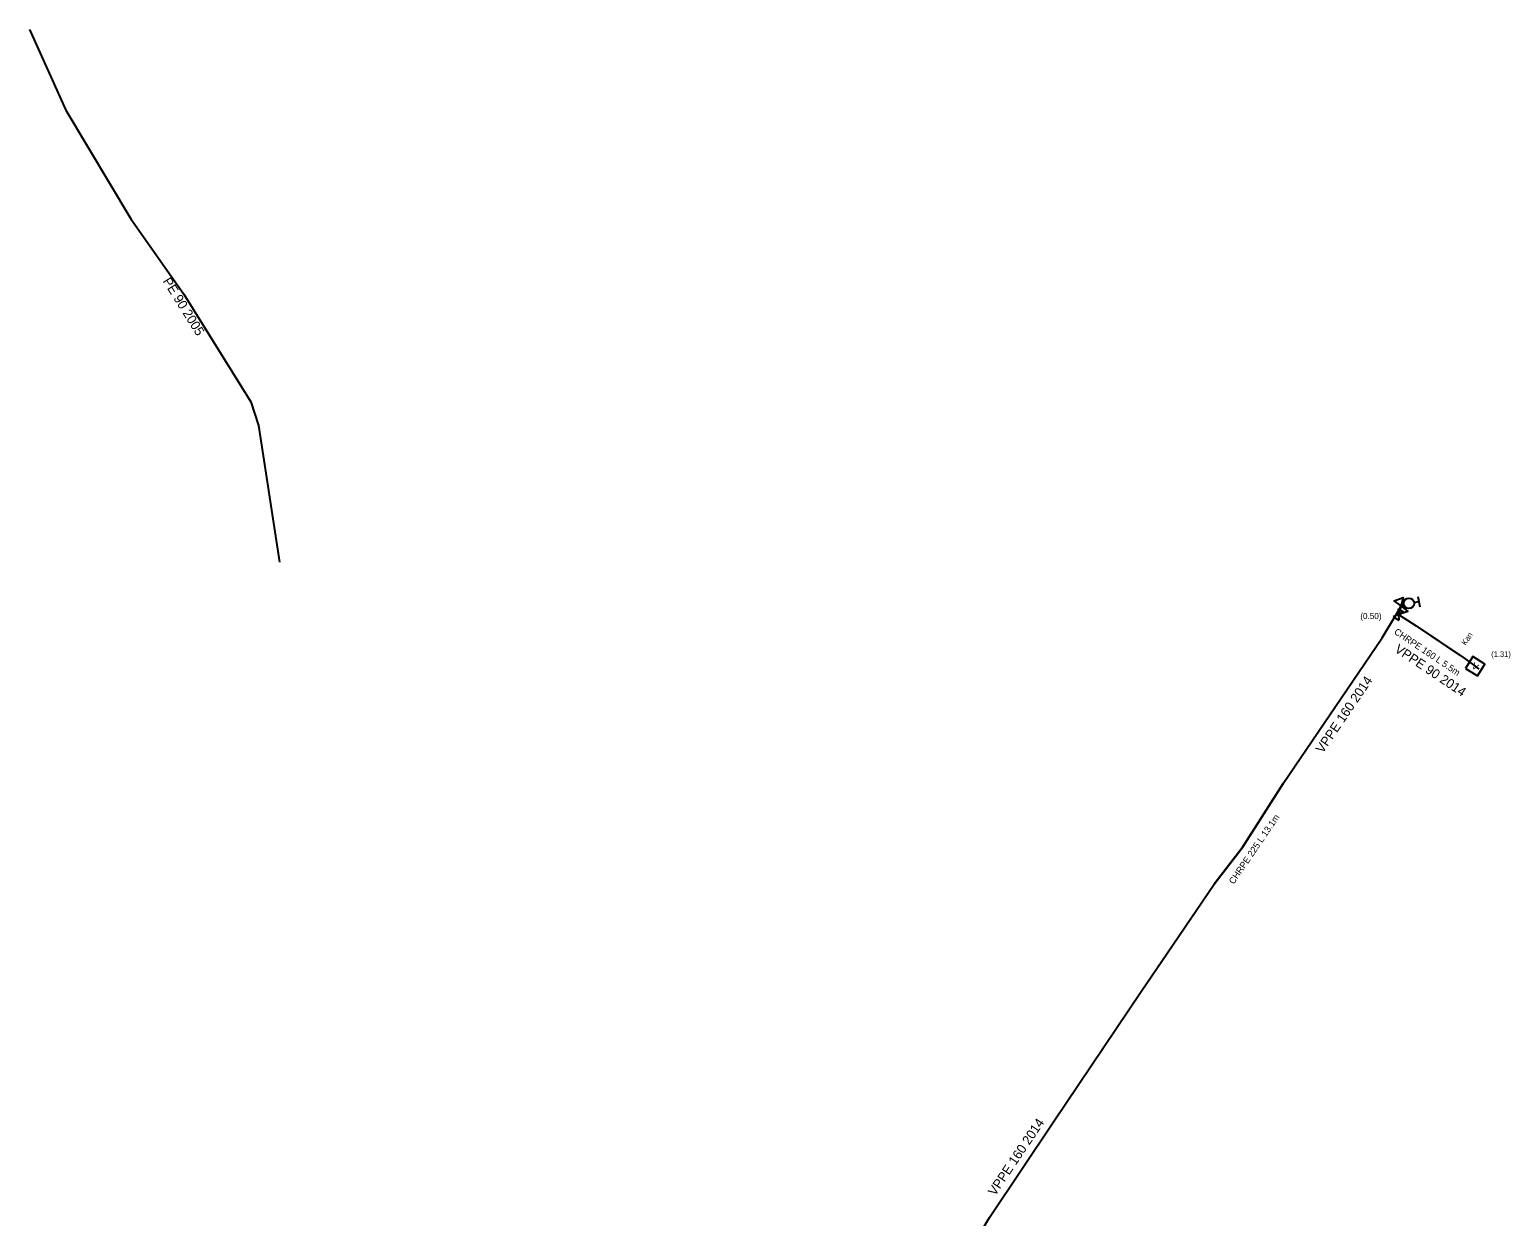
# Model space of a CAD drawing. Extents: x -539692 to -539259, y -1156467 to -1155971.
# Drawn here: x -539417.2 to -539259.2, y -1156098 to -1155971.4 of the extents above; entities that cross this region are included whole.
import ezdxf

# ---------------------------------------------------------------- set-up
doc = ezdxf.new("R2010")
doc.units = 0
for name, color, linetype in [('Vrstva 11', 7, 'Continuous'), ('Vrstva 15', 7, 'Continuous'), ('Vrstva 18', 7, 'Continuous'), ('Vrstva 26', 7, 'Continuous'), ('Vrstva 28', 7, 'Continuous'), ('Vrstva 32', 7, 'Continuous'), ('Vrstva 37', 7, 'Continuous'), ('Vrstva 55', 7, 'Continuous'), ('Vrstva 57', 7, 'Continuous'), ('Vrstva 58', 7, 'Continuous'), ('Vrstva 7', 7, 'Continuous')]:
    doc.layers.add(name, color=color, linetype=linetype)

msp = doc.modelspace()

# ---------------------------------------------------------------- linework, layer by layer
at = {"layer": 'Vrstva 11'}
for points in [[(-539417.223, -1155971.388), (-539413.37, -1155979.97), (-539406.41, -1155991.57), (-539400.77, -1155999.62), (-539393.6, -1156011.11), (-539392.8, -1156013.62), (-539390.54, -1156028.2)], [(-539271.31, -1156033.67), (-539271.12, -1156033.79)], [(-539271.12, -1156033.79), (-539269.25, -1156034.99), (-539264.25, -1156038.35), (-539263.78, -1156038.7), (-539262.95, -1156039.31)]]:
    msp.add_lwpolyline(points, dxfattribs=at)
at = {"layer": 'Vrstva 15'}
for p, q in [((-539413.37, -1155979.97), (-539406.41, -1155991.57)), ((-539264.47, -1156038.2), (-539269.05, -1156035.12))]:
    msp.add_line(p, q, dxfattribs=at)
msp.add_lwpolyline([(-539283.45, -1156051.82), (-539287.81, -1156058.68), (-539290.79, -1156062.56)], dxfattribs=at)
at = {"layer": 'Vrstva 18'}
msp.add_line((-539262.95, -1156039.31), (-539262.547, -1156039.606), dxfattribs=at)
at = {"layer": 'Vrstva 26'}
msp.add_lwpolyline([(-539270.85, -1156032.88), (-539271.584, -1156032.328), (-539270.623, -1156031.988), (-539271.078, -1156033.771), (-539270.117, -1156033.432), (-539270.85, -1156032.88)], dxfattribs=at)
at = {"layer": 'Vrstva 28'}
for p, q in [((-539269.471, -1156032.501), (-539268.967, -1156032.41)), ((-539269.066, -1156031.86), (-539268.867, -1156032.961))]:
    msp.add_line(p, q, dxfattribs=at)
msp.add_circle((-539270.02, -1156032.6), 0.559, dxfattribs=at)
at = {"layer": 'Vrstva 32'}
for p, q in [((-539271.159, -1156033.175), (-539271.083, -1156034.406)), ((-539271.159, -1156033.175), (-539270.553, -1156033.549)), ((-539270.553, -1156033.549), (-539271.687, -1156034.031)), ((-539271.687, -1156034.031), (-539271.083, -1156034.406))]:
    msp.add_line(p, q, dxfattribs=at)
at = {"layer": 'Vrstva 37'}
msp.add_lwpolyline([(-539263.983, -1156039.548), (-539262.712, -1156040.344), (-539261.917, -1156039.072), (-539263.189, -1156038.276)], close=True, dxfattribs=at)
at = {"layer": 'Vrstva 7'}
for points in [[(-539271.31, -1156033.67), (-539270.85, -1156032.88)], [(-539270.85, -1156032.88), (-539270.57, -1156032.7)], [(-539295.78, -1156069.878), (-539290.79, -1156062.56), (-539287.81, -1156058.68), (-539283.45, -1156051.82), (-539272.86, -1156036.29), (-539271.31, -1156033.67)], [(-539332.81, -1156124.85), (-539331.81, -1156123.34), (-539319.14, -1156104.79), (-539317.13, -1156102.06), (-539314.79, -1156098.13), (-539307.94, -1156087.91), (-539298.59, -1156074), (-539295.78, -1156069.878)]]:
    msp.add_lwpolyline(points, dxfattribs=at)

# ---------------------------------------------------------------- texts
at = {"layer": 'Vrstva 37'}
msp.add_text('V', height=0.7, rotation=327.98803, dxfattribs=at).set_placement((-539263.395, -1156039.445))
at = {"layer": 'Vrstva 55'}
for s, rotation, p in [('PE 90 2005', 301.96502, (-539403.056, -1155998.222)), ('VPPE 90 2014', 326.07963, (-539271.628, -1156037.709)), ('VPPE 160 2014', 55.70973, (-539279.22, -1156048.67)), ('VPPE 160 2014', 56.16783, (-539314.18, -1156095.89))]:
    msp.add_text(s, height=1, rotation=rotation, dxfattribs=at).set_placement(p)
at = {"layer": 'Vrstva 57'}
for s, rotation, p in [('CHRPE 160 L 5.5m', 326.07963, (-539271.667, -1156035.792)), ('CHRPE 225 L 13.1m', 55.71315, (-539288.713, -1156062.629))]:
    msp.add_text(s, height=0.7, rotation=rotation, dxfattribs=at).set_placement(p)
at = {"layer": 'Vrstva 58'}
for s, height, p in [('(0.50)', 0.65, (-539275.206, -1156034.278)), ('(1.31)', 0.6, (-539261.236, -1156038.311))]:
    msp.add_text(s, height=height, dxfattribs=at).set_placement(p)
msp.add_text('Kan', height=0.6, rotation=56.07963, dxfattribs=at).set_placement((-539263.963, -1156037.13))

doc.saveas('drawing.dxf')
